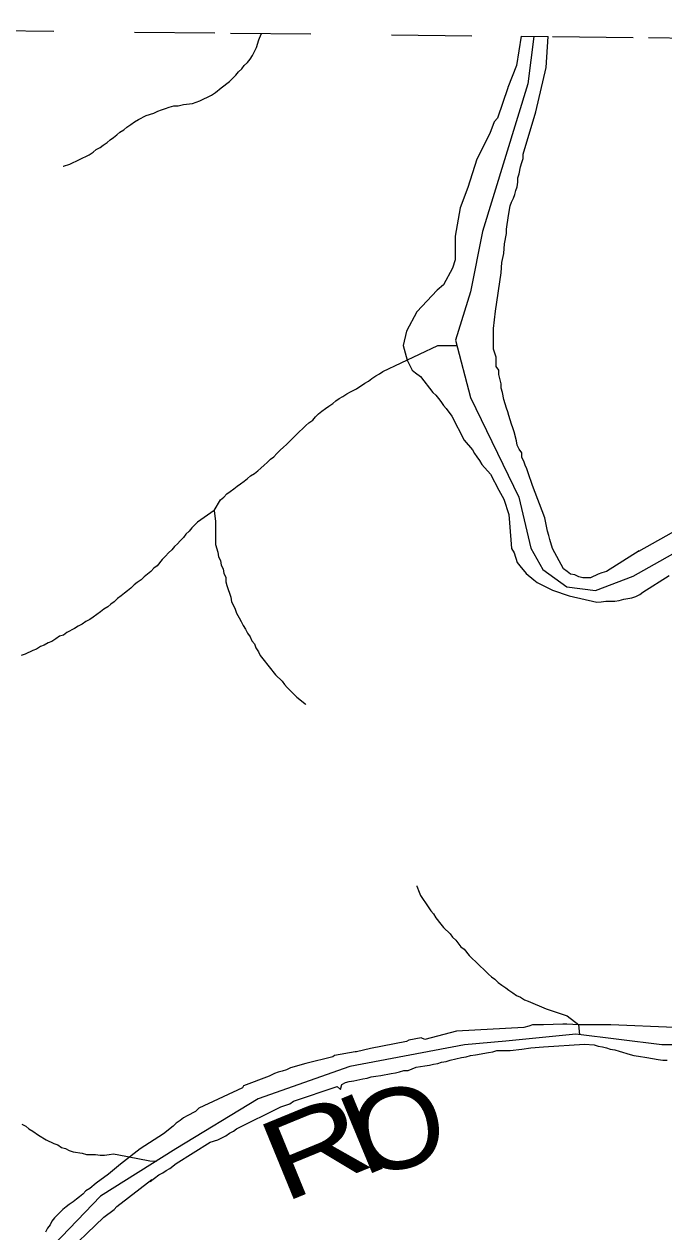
# Model space of a CAD drawing. Extents: x 652.3 to 678, y 7316.9 to 7344.9.
# Drawn here: x 653.367 to 654.161, y 7343.427 to 7344.926 of the extents above; entities that cross this region are included whole.
import ezdxf
from ezdxf.enums import TextEntityAlignment as Align

# ---------------------------------------------------------------- set-up
doc = ezdxf.new("R2010")
doc.units = 0
doc.header["$LTSCALE"] = 0.032
doc.linetypes.add('SHORT_DASHED', pattern=[2.7, 1.5, -1.2])
for name, color, linetype, lineweight in [('2', 7, 'Continuous', 25), ('53', 7, 'SHORT_DASHED', 13), ('55', 7, 'Continuous', 25), ('7', 7, 'Continuous', 25)]:
    doc.layers.add(name, color=color, linetype=linetype, lineweight=lineweight)
doc.layers.add('61', color=7, linetype='Continuous')

msp = doc.modelspace()

# ---------------------------------------------------------------- linework, layer by layer
at = {"layer": '2'}
for p in [(653.9838, 7344.9107), (654.0148, 7344.8719)]:
    msp.add_line(p, (654.0174, 7344.9103), dxfattribs=at)
for points in [[(653.9838, 7344.9107), (653.9782, 7344.8743), (653.9782, 7344.8743), (653.9671, 7344.8473), (653.9671, 7344.8465), (653.9543, 7344.8091), (653.9504, 7344.8043), (653.9448, 7344.79), (653.9289, 7344.7581), (653.9289, 7344.7581), (653.9177, 7344.7231), (653.9177, 7344.7231), (653.9082, 7344.6977), (653.9082, 7344.6977), (653.9018, 7344.6627), (653.9018, 7344.6627), (653.9018, 7344.6372), (653.9018, 7344.6332), (653.8986, 7344.6229), (653.8875, 7344.6022), (653.8796, 7344.5958), (653.8541, 7344.5688), (653.8541, 7344.5688), (653.8414, 7344.5449), (653.8414, 7344.5449), (653.8374, 7344.5269)], [(654.1803, 7344.2998), (654.1294, 7344.2712), (654.1302, 7344.272), (654.0896, 7344.2465), (654.084, 7344.2449), (654.0793, 7344.2433), (654.0697, 7344.2386), (654.0602, 7344.2386), (654.0554, 7344.2401), (654.0506, 7344.2425), (654.0451, 7344.2433), (654.0411, 7344.2465), (654.0363, 7344.2497), (654.0228, 7344.2752), (654.0196, 7344.2863), (654.018, 7344.2911), (654.0164, 7344.2966), (654.0132, 7344.3133), (653.9981, 7344.3531), (653.9925, 7344.369), (653.9909, 7344.3738), (653.9886, 7344.3786), (653.987, 7344.3834), (653.9846, 7344.3881), (653.9846, 7344.3937), (653.9814, 7344.3985), (653.979, 7344.4033), (653.9782, 7344.4088), (653.975, 7344.42), (653.9734, 7344.4247), (653.9718, 7344.4295), (653.9687, 7344.4399), (653.9671, 7344.4446), (653.9655, 7344.4494), (653.9623, 7344.4598), (653.9607, 7344.4685), (653.9591, 7344.4741), (653.9591, 7344.4796), (653.9559, 7344.4908), (653.9559, 7344.4964), (653.9528, 7344.5011), (653.9528, 7344.5067), (653.9528, 7344.5123), (653.9496, 7344.5226), (653.9496, 7344.5353), (653.9496, 7344.5481), (653.952, 7344.5696), (653.9591, 7344.6173), (653.9599, 7344.63), (653.9623, 7344.6412), (653.9631, 7344.6531), (653.9655, 7344.6658), (653.9655, 7344.6714), (653.9679, 7344.6881), (653.9703, 7344.7001), (653.9718, 7344.7048), (653.9742, 7344.7096), (653.9758, 7344.7144), (653.9774, 7344.7191), (653.979, 7344.7239), (653.9798, 7344.7295), (653.9798, 7344.7351), (653.9814, 7344.7398), (653.983, 7344.7486), (653.9846, 7344.7542), (653.9862, 7344.7589), (653.9862, 7344.7645), (654.0021, 7344.817), (654.0021, 7344.817), (654.0148, 7344.8719)], [(653.8374, 7344.5269), (653.8374, 7344.5269), (653.8421, 7344.5087)], [(653.8421, 7344.5087), (653.8485, 7344.4964), (653.8525, 7344.4932), (653.8589, 7344.4884), (653.874, 7344.4685), (653.878, 7344.4653), (653.8811, 7344.4613), (653.8843, 7344.4574), (653.8875, 7344.4526), (653.8907, 7344.4486), (653.8979, 7344.4391), (653.913, 7344.4096), (653.9233, 7344.3977), (653.9257, 7344.3929), (653.9289, 7344.3889), (653.9321, 7344.3842), (653.9352, 7344.3794), (653.9456, 7344.3675), (653.9559, 7344.3476), (653.9623, 7344.3364), (653.9687, 7344.3173), (653.9695, 7344.307), (653.9718, 7344.2752), (653.975, 7344.2696)], [(653.975, 7344.2696), (653.979, 7344.2576), (653.9822, 7344.2537), (653.9902, 7344.2441), (653.9997, 7344.2362), (654.0037, 7344.233), (654.0228, 7344.2234), (654.0435, 7344.2163)], [(654.0435, 7344.2163), (654.0777, 7344.2083), (654.0832, 7344.2091), (654.0888, 7344.2099), (654.0944, 7344.2099), (654.1, 7344.2099), (654.1055, 7344.2107), (654.1111, 7344.2123), (654.1214, 7344.2139), (654.1262, 7344.2155), (654.131, 7344.2179), (654.135, 7344.221), (654.1676, 7344.2417)], [(654.3848, 7343.8073), (654.3633, 7343.7699), (654.3562, 7343.7564), (654.345, 7343.7389), (654.3029, 7343.6983), (654.2933, 7343.6903), (654.2631, 7343.6784), (654.2487, 7343.6736), (654.2018, 7343.6776), (654.1843, 7343.6792), (654.174, 7343.6808), (654.0952, 7343.684), (654.0737, 7343.684), (654.0737, 7343.684), (654.0554, 7343.684), (654.0554, 7343.684)], [(654.0407, 7343.6847), (654.0355, 7343.6848), (654.0116, 7343.684), (653.9981, 7343.684), (653.9933, 7343.6824), (653.987, 7343.6808), (653.9034, 7343.676), (653.9034, 7343.676), (653.8644, 7343.6657), (653.8597, 7343.668), (653.8445, 7343.6649), (653.8414, 7343.6633), (653.7968, 7343.6545), (653.7793, 7343.6505), (653.7777, 7343.6505), (653.7522, 7343.6458), (653.7499, 7343.6442), (653.7164, 7343.6362), (653.6973, 7343.6306), (653.6926, 7343.6283), (653.687, 7343.6267), (653.6822, 7343.6251), (653.6774, 7343.6235), (653.6727, 7343.6211), (653.6711, 7343.6203), (653.6393, 7343.6084), (653.6377, 7343.606), (653.5836, 7343.5805), (653.5796, 7343.5765), (653.5692, 7343.571), (653.5645, 7343.5686), (653.5605, 7343.5654), (653.5557, 7343.5622), (653.5517, 7343.5582), (653.5398, 7343.5487), (653.5109, 7343.5303), (653.5109, 7343.5303)], [(654.0554, 7343.684), (654.0554, 7343.684), (654.0407, 7343.6847)], [(653.7594, 7343.6036), (653.761, 7343.61), (653.7658, 7343.6123), (653.7705, 7343.6139), (653.7761, 7343.6147), (653.7873, 7343.6171), (653.7928, 7343.6179), (653.7976, 7343.6195), (653.8032, 7343.6203), (653.8095, 7343.6211), (653.8223, 7343.6235), (653.8278, 7343.6243), (653.8326, 7343.6259), (653.8382, 7343.6275), (653.8437, 7343.6275), (653.8533, 7343.6314), (653.8589, 7343.6322), (653.8644, 7343.633), (653.87, 7343.6338), (653.8748, 7343.6354), (653.8803, 7343.6362), (653.8851, 7343.6378), (653.8907, 7343.6386), (653.8955, 7343.6402), (653.9098, 7343.6434), (653.9154, 7343.6442), (653.9209, 7343.6458), (653.9273, 7343.6466), (653.9432, 7343.6497), (653.9488, 7343.6505), (653.9535, 7343.6521), (653.9591, 7343.6521), (653.9647, 7343.6521), (653.9703, 7343.6521), (653.9846, 7343.6537), (653.9957, 7343.6553), (654.0116, 7343.6569), (654.0626, 7343.6601), (654.0745, 7343.6593), (654.0793, 7343.6577), (654.0848, 7343.6569), (654.0896, 7343.6553), (654.0944, 7343.6537), (654.1, 7343.6529), (654.1055, 7343.6513), (654.1191, 7343.6474), (654.1238, 7343.6458), (654.1294, 7343.645), (654.1397, 7343.6434), (654.1541, 7343.641), (654.1596, 7343.6402), (654.1652, 7343.6402)], [(653.4133, 7343.3951), (653.4658, 7343.4453), (653.4785, 7343.4548), (653.4817, 7343.4588), (653.5255, 7343.4922), (653.5231, 7343.4898), (653.5342, 7343.4978), (653.539, 7343.5002), (653.543, 7343.5033), (653.5477, 7343.5057), (653.5557, 7343.5121), (653.5979, 7343.5383), (653.6074, 7343.5415), (653.6122, 7343.5439), (653.617, 7343.5463), (653.6217, 7343.5495), (653.6265, 7343.5519), (653.6305, 7343.5551), (653.6854, 7343.5821), (653.6965, 7343.5861), (653.7013, 7343.5893), (653.7554, 7343.6076), (653.7594, 7343.6036)], [(653.5109, 7343.5303), (653.5109, 7343.5303), (653.4865, 7343.5111)], [(653.4865, 7343.5111), (653.4714, 7343.4986), (653.4562, 7343.4874), (653.4483, 7343.4811), (653.4435, 7343.4779), (653.4395, 7343.4739), (653.4356, 7343.4707), (653.4316, 7343.4675), (653.4276, 7343.4643), (653.4228, 7343.4612), (653.4188, 7343.458), (653.4149, 7343.4548), (653.4045, 7343.4445), (653.4013, 7343.4405), (653.399, 7343.4357), (653.3958, 7343.4317), (653.3934, 7343.4269)]]:
    msp.add_lwpolyline(points, dxfattribs=at)
at = {"layer": '53'}
msp.add_lwpolyline([(652.5847, 7344.9257), (653.1037, 7344.9201), (653.6228, 7344.9146), (654.1419, 7344.909), (654.661, 7344.9034), (655.1801, 7344.8978), (655.6991, 7344.8922), (656.2182, 7344.8865), (656.7373, 7344.8808), (657.2564, 7344.8752), (657.7755, 7344.8694), (658.2945, 7344.8637), (658.8136, 7344.858), (659.3327, 7344.8522)], dxfattribs=at)
at = {"layer": '55'}
for p, q in [((654.0568, 7343.6719), (654.0554, 7343.684)), ((653.4953, 7343.5208), (653.5227, 7343.5151)), ((653.5227, 7343.5151), (653.5312, 7343.515))]:
    msp.add_line(p, q, dxfattribs=at)
for points in [[(653.9995, 7344.9105), (653.992, 7344.8518), (653.9359, 7344.6684), (653.9209, 7344.5935), (653.9022, 7344.5336), (653.9209, 7344.4625), (653.9808, 7344.3389), (653.9958, 7344.2753), (654.0107, 7344.249), (654.0404, 7344.2273), (654.076, 7344.2228), (654.1228, 7344.2406), (654.2809, 7344.3297)], [(653.8119, 7344.4948), (653.8804, 7344.527), (653.904, 7344.527)], [(654.2341, 7343.6592), (654.1584, 7343.6592), (654.105, 7343.6659), (654.0515, 7343.6726), (653.9647, 7343.6637), (653.9135, 7343.6592), (653.771, 7343.6325), (653.6575, 7343.5924), (653.5551, 7343.53), (653.4615, 7343.4713), (653.4037, 7343.4111)]]:
    msp.add_lwpolyline(points, dxfattribs=at)
at = {"layer": '7'}
for p, q in [((653.6591, 7344.9084), (653.6615, 7344.9142)), ((653.4843, 7343.5228), (653.4953, 7343.5208))]:
    msp.add_line(p, q, dxfattribs=at)
for points in [[(653.4153, 7344.7493), (653.4157, 7344.7494), (653.4236, 7344.7518), (653.4475, 7344.7637), (653.4523, 7344.7669), (653.4562, 7344.7701), (653.461, 7344.7725), (653.465, 7344.7756), (653.4698, 7344.7788), (653.4737, 7344.782), (653.4777, 7344.7852), (653.4817, 7344.7884), (653.4857, 7344.7916), (653.4905, 7344.7947), (653.4944, 7344.7979), (653.4992, 7344.8011), (653.504, 7344.8043), (653.5088, 7344.8075), (653.5183, 7344.8122), (653.5279, 7344.8154), (653.5326, 7344.8178), (653.5374, 7344.8194), (653.5422, 7344.821), (653.547, 7344.8226), (653.5525, 7344.8242), (653.5581, 7344.8242), (653.5645, 7344.8258), (653.5756, 7344.8274), (653.5851, 7344.8305), (653.5995, 7344.8377), (653.6042, 7344.8409), (653.6114, 7344.8465), (653.6217, 7344.8544), (653.6297, 7344.8624), (653.6329, 7344.8664), (653.6369, 7344.8703), (653.64, 7344.8743), (653.644, 7344.8783), (653.6472, 7344.8823), (653.6504, 7344.887), (653.6528, 7344.8918), (653.6552, 7344.8966), (653.6583, 7344.9061), (653.6591, 7344.9084)], [(653.6027, 7344.3221), (653.6106, 7344.3356), (653.6146, 7344.3388), (653.6186, 7344.3428), (653.6225, 7344.346), (653.6273, 7344.3492), (653.6313, 7344.3523), (653.6353, 7344.3555), (653.64, 7344.3587), (653.644, 7344.3619), (653.648, 7344.3651), (653.6528, 7344.3682), (653.6568, 7344.3714), (653.6607, 7344.3746), (653.6647, 7344.3786), (653.6687, 7344.3818), (653.6727, 7344.3858), (653.6766, 7344.3889), (653.6806, 7344.3929), (653.6846, 7344.3969), (653.6886, 7344.4009), (653.6926, 7344.4041), (653.7005, 7344.412), (653.7045, 7344.416), (653.7164, 7344.4279), (653.7204, 7344.4311), (653.7252, 7344.4343), (653.7284, 7344.4383), (653.7323, 7344.4422), (653.7363, 7344.4454), (653.7411, 7344.4486), (653.7451, 7344.4518), (653.7499, 7344.455), (653.7538, 7344.4582), (653.7578, 7344.4613), (653.7626, 7344.4637), (653.7674, 7344.4669), (653.7721, 7344.4693), (653.7793, 7344.4733), (653.7896, 7344.4804), (653.7944, 7344.4828), (653.7984, 7344.486), (653.8032, 7344.4892), (653.8079, 7344.4916), (653.8119, 7344.4948)], [(653.6027, 7344.3221), (653.582, 7344.3078), (653.5748, 7344.3006), (653.5716, 7344.2966), (653.5676, 7344.2927), (653.5645, 7344.2887), (653.5605, 7344.2847), (653.5573, 7344.2807), (653.5533, 7344.2775), (653.5501, 7344.2736), (653.5462, 7344.2696), (653.5422, 7344.2656), (653.5382, 7344.2616), (653.5318, 7344.2537), (653.5279, 7344.2505), (653.5239, 7344.2465), (653.5199, 7344.2433), (653.5159, 7344.2401), (653.5119, 7344.2362), (653.5072, 7344.233), (653.5032, 7344.2298), (653.4992, 7344.2258), (653.4952, 7344.2226), (653.4913, 7344.2195), (653.4873, 7344.2163), (653.4825, 7344.2131), (653.4785, 7344.2091), (653.4745, 7344.2059), (653.4706, 7344.2027), (653.4658, 7344.1996), (653.4618, 7344.1964), (653.457, 7344.1932), (653.4523, 7344.19), (653.4483, 7344.1868), (653.4435, 7344.1844), (653.4387, 7344.1813), (653.434, 7344.1789), (653.4292, 7344.1757), (653.4196, 7344.1709), (653.4157, 7344.1677), (653.4109, 7344.1661), (653.4061, 7344.163), (653.4013, 7344.1598), (653.3966, 7344.1582), (653.3918, 7344.155), (653.387, 7344.1534), (653.3822, 7344.1502), (653.3775, 7344.1486), (653.3679, 7344.1439), (653.3631, 7344.1423)], [(653.6027, 7344.3221), (653.6042, 7344.3086), (653.6042, 7344.2799), (653.6074, 7344.2704), (653.6082, 7344.2648), (653.6106, 7344.26), (653.6114, 7344.2545), (653.6138, 7344.2497), (653.6146, 7344.2441), (653.617, 7344.2393), (653.617, 7344.2338), (653.6186, 7344.229), (653.6233, 7344.2147), (653.6241, 7344.2091), (653.6265, 7344.2043), (653.6289, 7344.1996), (653.6305, 7344.1948), (653.6337, 7344.1892), (653.6361, 7344.1844), (653.6385, 7344.1797), (653.6416, 7344.1749), (653.644, 7344.1701), (653.6472, 7344.1653), (653.6496, 7344.1606), (653.6528, 7344.1566), (653.6544, 7344.1518), (653.6576, 7344.147), (653.6599, 7344.1423), (653.6631, 7344.1383), (653.679, 7344.1184), (653.687, 7344.1104), (653.6902, 7344.1065), (653.6934, 7344.1025), (653.7053, 7344.0906), (653.7133, 7344.0842), (653.7157, 7344.0822), (653.7164, 7344.0817)], [(653.8542, 7343.8564), (653.8543, 7343.8561), (653.8573, 7343.8487), (653.8589, 7343.8447), (653.8684, 7343.8304), (653.8716, 7343.8256), (653.8748, 7343.8216), (653.878, 7343.8168), (653.8843, 7343.8089), (653.8875, 7343.8049), (653.8955, 7343.7969), (653.8986, 7343.793), (653.9026, 7343.789), (653.909, 7343.781), (653.913, 7343.7778), (653.9193, 7343.7699), (653.9233, 7343.7659), (653.9273, 7343.7627), (653.9432, 7343.7468), (653.9472, 7343.7436), (653.9512, 7343.7405), (653.9551, 7343.7365), (653.9599, 7343.7333), (653.9647, 7343.7301), (653.9687, 7343.7269), (653.9734, 7343.7237), (653.9782, 7343.7206), (653.983, 7343.7182), (653.9878, 7343.715), (653.9925, 7343.7134), (654.0148, 7343.7038), (654.0411, 7343.6951)], [(654.0411, 7343.6951), (654.0554, 7343.684), (654.0554, 7343.684)], [(653.3639, 7343.5606), (653.3687, 7343.5582), (653.3727, 7343.5551), (653.3775, 7343.5519), (653.3846, 7343.5471), (653.3942, 7343.5415), (653.4037, 7343.5368), (653.4085, 7343.5352), (653.4133, 7343.532), (653.4181, 7343.5304), (653.4228, 7343.528), (653.4276, 7343.5264), (653.4387, 7343.5248), (653.4443, 7343.5232), (653.4554, 7343.5232), (653.461, 7343.5224), (653.4666, 7343.5224), (653.4722, 7343.5232), (653.4777, 7343.524), (653.4844, 7343.5228)]]:
    msp.add_lwpolyline(points, dxfattribs=at)

# ---------------------------------------------------------------- texts
at = {"layer": '61'}
for s, rotation, width, p in [('O', 11.87, 1.1, (653.8416, 7343.5068)), ('R', 22.302, 1.3, (653.7463, 7343.4863)), ('I', 22.521, 1.15, (653.8054, 7343.5028))]:
    msp.add_text(s, height=0.1, rotation=rotation, dxfattribs=dict(at, width=width)).set_placement(p, align=Align.CENTER)

doc.saveas('drawing.dxf')
